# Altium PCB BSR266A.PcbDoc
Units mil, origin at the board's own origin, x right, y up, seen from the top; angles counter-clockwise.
Board outline 1624.02 x 1771.65 mil, 4 copper layers (Top Layer, GND 01, GND 02, Bottom Layer), stack 60.4 mil thick; 39 components, 9 nets, 52 pads, 271 vias.
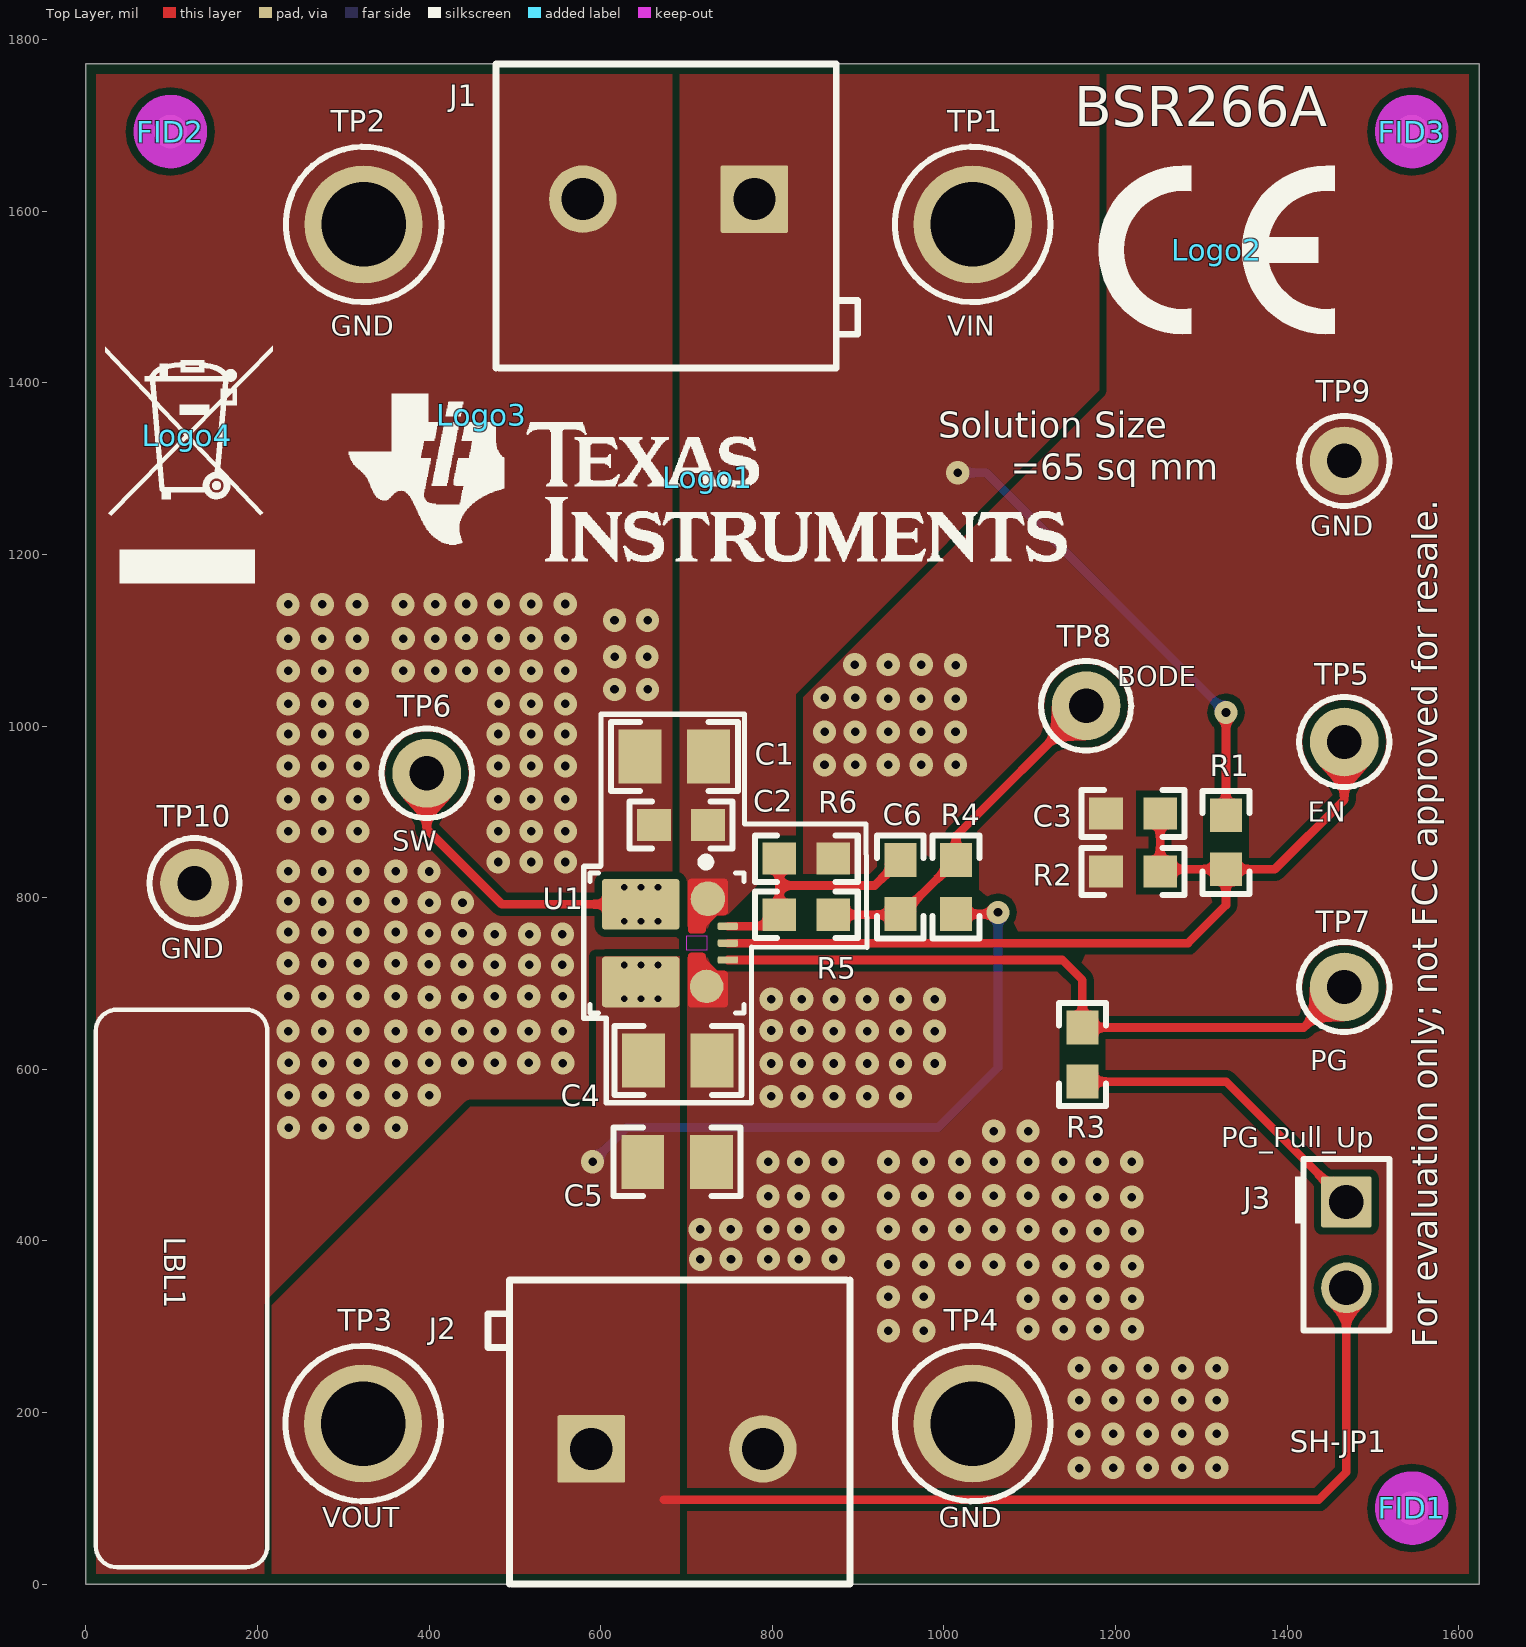
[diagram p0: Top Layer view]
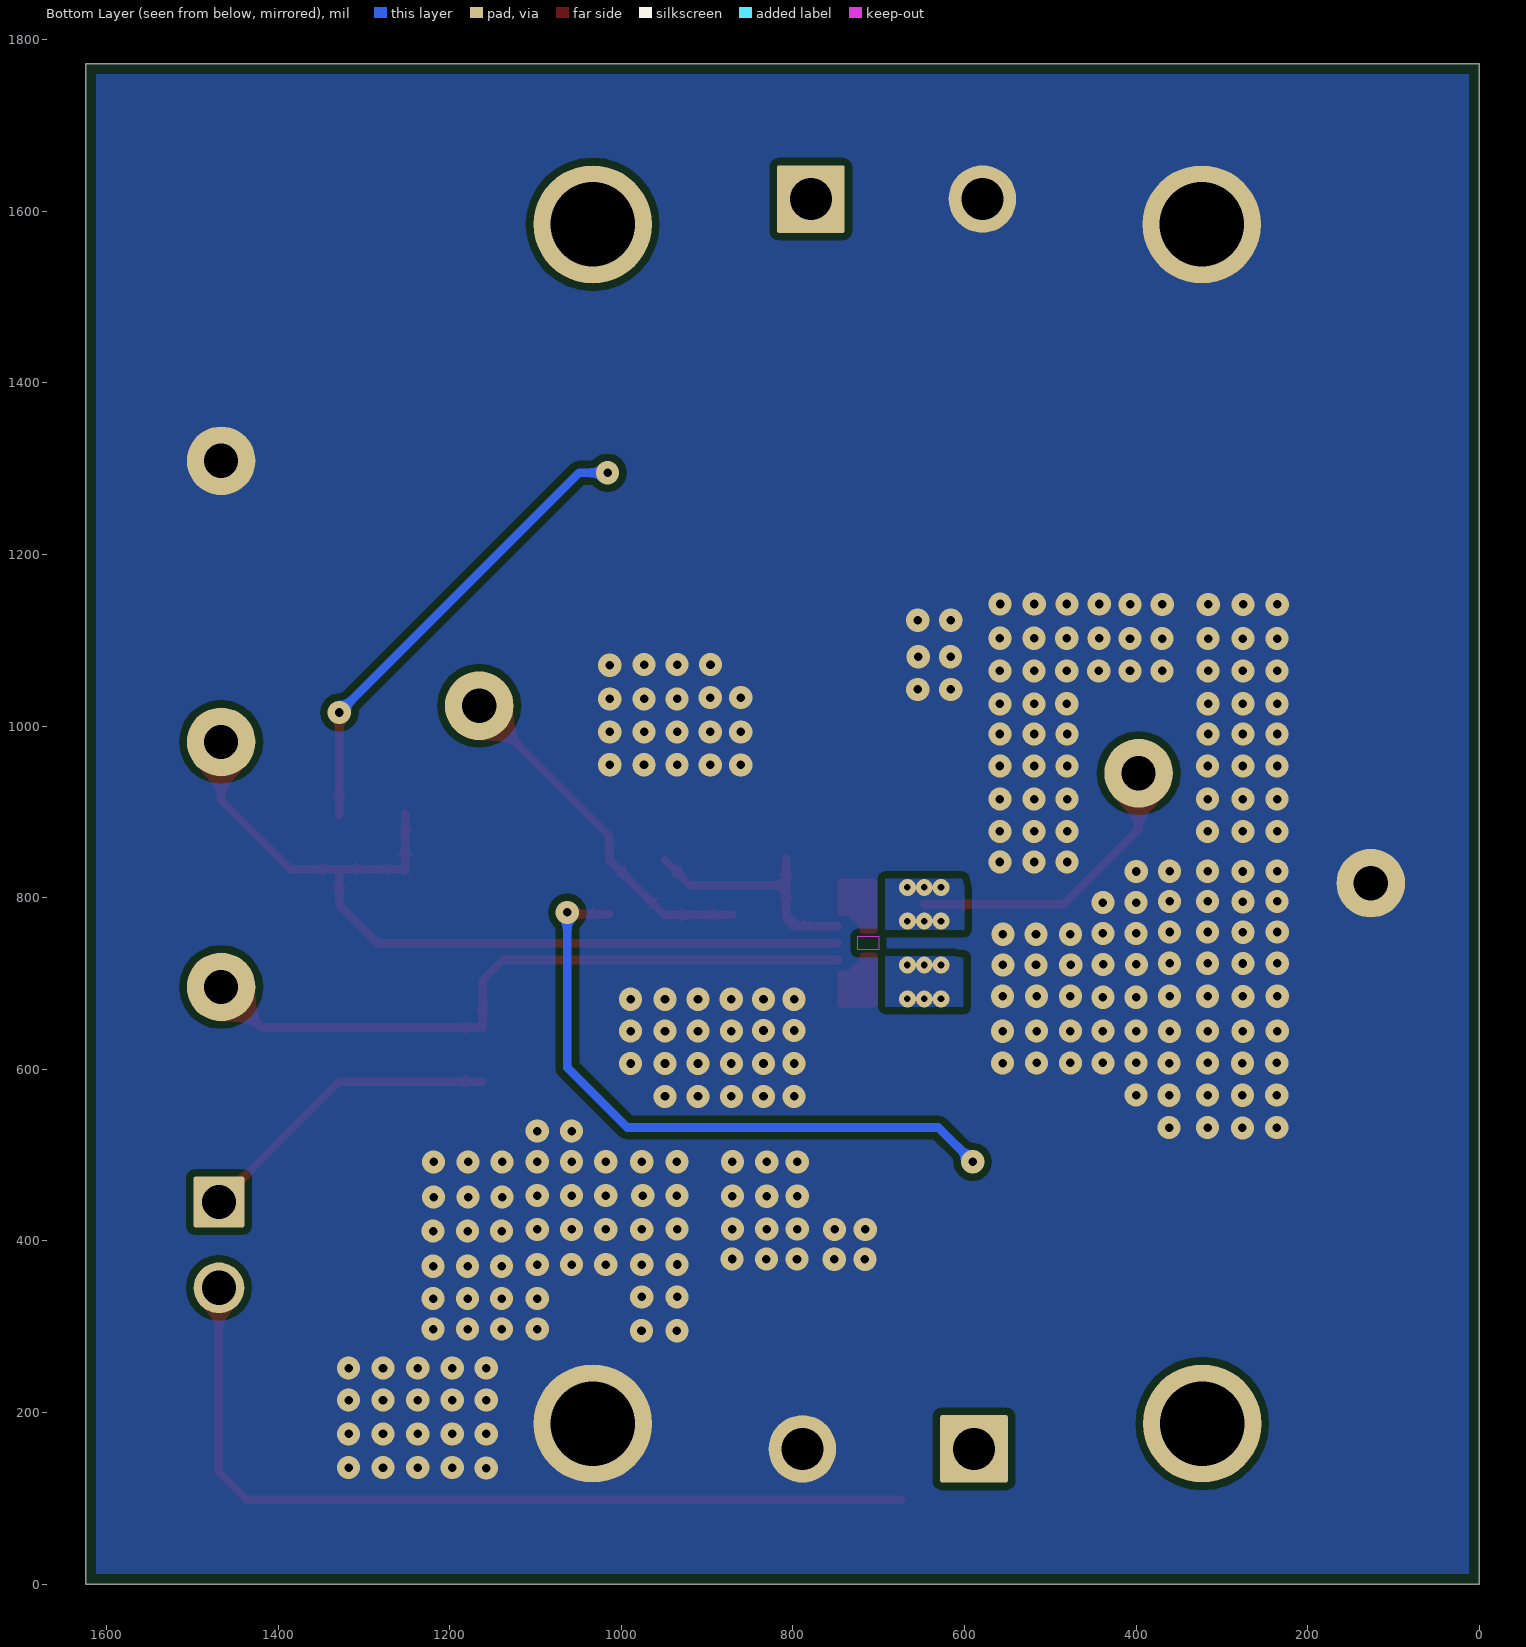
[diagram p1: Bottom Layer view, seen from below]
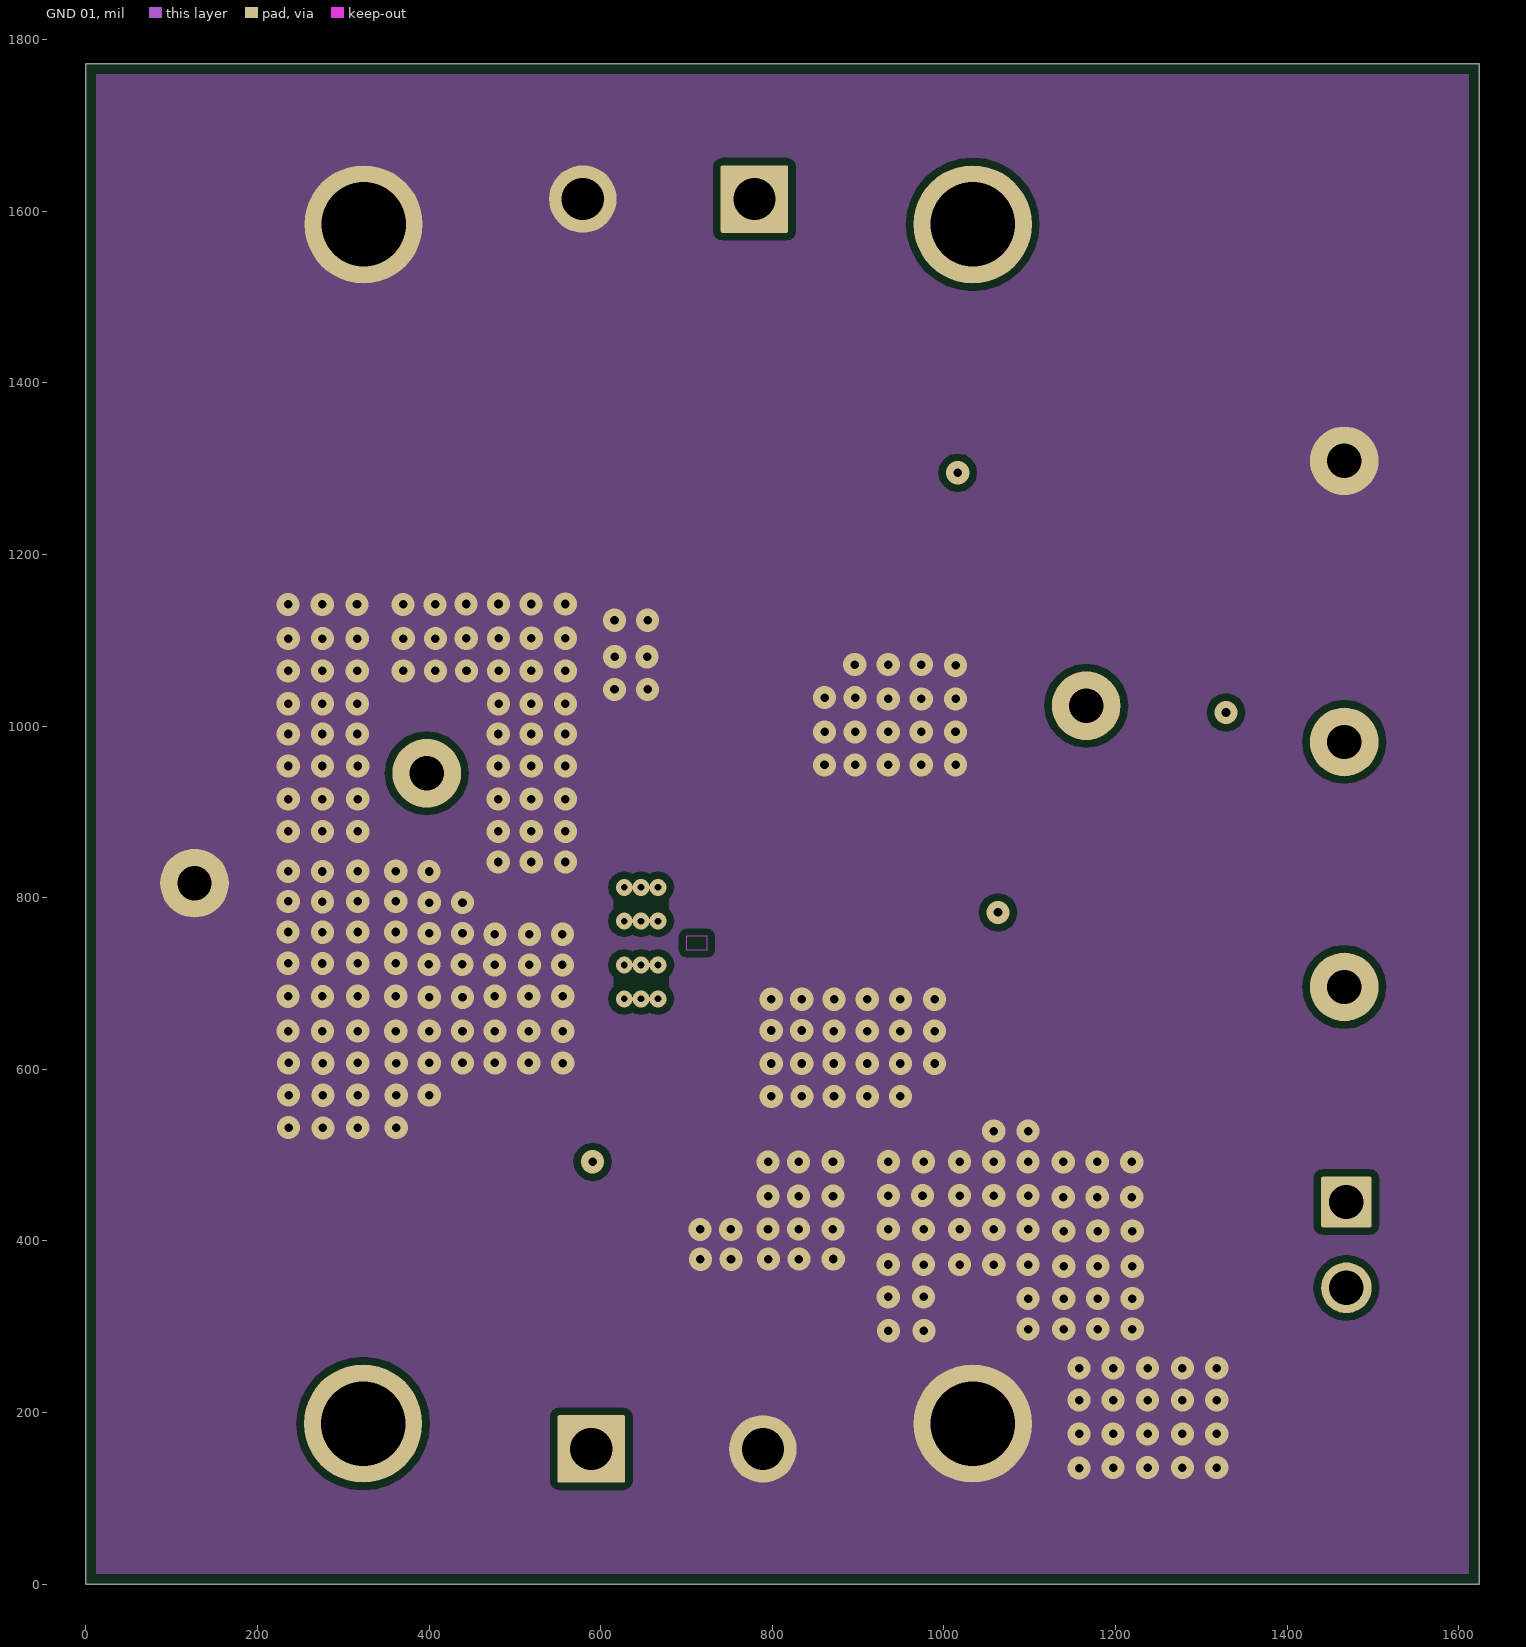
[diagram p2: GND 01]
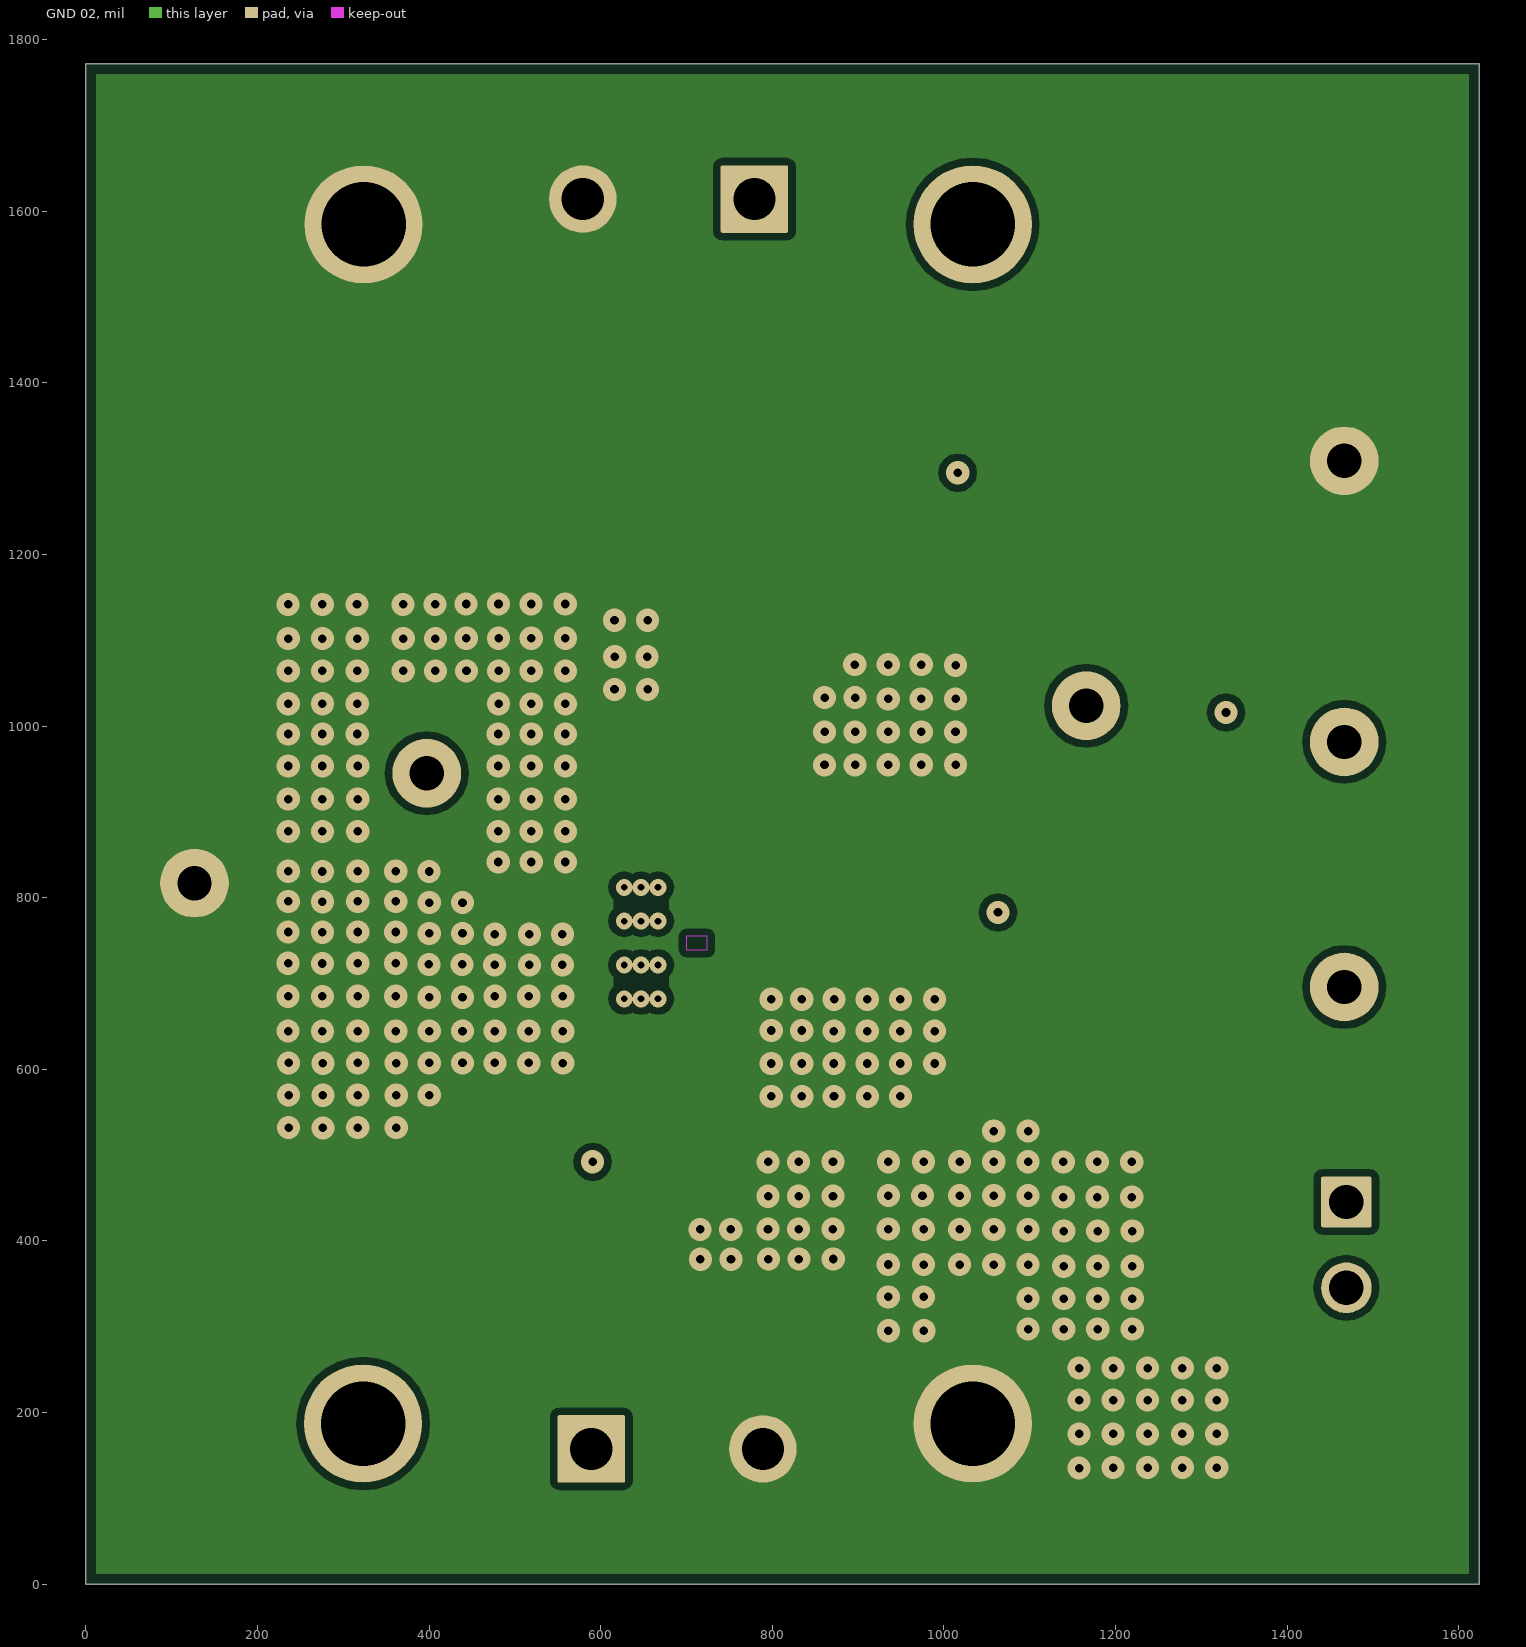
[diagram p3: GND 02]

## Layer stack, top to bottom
Top Solder: solder mask 0.4, Solder Resist, Dk 3.5
Top Layer: signal copper 2.8
Dielectric 1: core 6, FR-4 High Tg, Dk 4.8
GND 01: signal copper 1.4
Dielectric 2: prepreg 40, FR-4 High Tg, Dk 4.8
GND 02: signal copper 1.4
Dielectric 3: core 6, FR-4 High Tg, Dk 4.2
Bottom Layer: signal copper 2.8
Bottom Solder: solder mask 0.4, Solder Resist, Dk 3.5

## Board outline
0,0 0,1771.65 1624.02,1771.65 1624.02,0

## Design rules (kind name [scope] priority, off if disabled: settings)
AcuteAngle [All] p1: minimum=4.50000000000000E+0001 checktracksonly=FALSE
AssemblyTestPointUsage [All] p1: valid=2
BoardOutlineClearance BoardOutlineClearance_MountingHoles [OnCopper and InComponentClass('Mounting Holes')] p1: gap=40 ignorepadtopadclearanceinfootprint=FALSE
BoardOutlineClearance BoardOutlineClearance_Poly [OnCopper and IsPoly] p2: gap=12 ignorepadtopadclearanceinfootprint=FALSE
BoardOutlineClearance [OnCopper and Not InComponentClass('Logo') and not InComponentClass('FiducialMark') and not InRegion(1000,500,4000,800) and not InPoly] p3: gap=75 ignorepadtopadclearanceinfootprint=FALSE
Clearance Clearance_Keepouts [((IsTrack Or IsArc) And Not InPoly) And IsFree and IsKeepOut vs ((IsTrack Or IsArc) And Not InPoly) And IsFree and IsKeepOut] p1: gap=0 ignorepadtopadclearanceinfootprint=FALSE
Clearance Clearance_Poly [InPolygon] p2: gap=8.5 ignorepadtopadclearanceinfootprint=TRUE except(0: Arc-Hole Track-Hole SMDPad-Hole THPad-Hole Via-Hole Fill-Hole Poly-Hole Region-Hole Text-Hole)
Clearance [All] p3: gap=5 ignorepadtopadclearanceinfootprint=FALSE except(0: Arc-Hole Track-Hole SMDPad-Hole THPad-Hole Via-Hole Fill-Hole Poly-Hole Region-Hole Text-Hole)
ComponentClearance ComponentClearance_MountingHoles_FiducialMarks [InComponentClass('Mounting Holes') vs InComponentClass('FiducialMark')] p1: gap=50 collisioncheckmode=3 verticalgap=10 showdistances=FALSE
ComponentClearance ComponentClearance_Shunt [InComponentClass('Header') vs InComponentClass('Shunt')] p2: gap=0 collisioncheckmode=3 verticalgap=0 showdistances=FALSE
ComponentClearance ComponentClearance_Logo [InComponentClass('Logo')] p3: gap=50 collisioncheckmode=3 verticalgap=10 showdistances=FALSE
ComponentClearance ComponentClearance_ScrewToNut [(HasFootprint('NY PMS 440 0025 PH')) vs (HasFootprint('Keystone_1902C'))] p4: gap=5 collisioncheckmode=3 verticalgap=10 showdistances=FALSE
ComponentClearance ComponentClearance_MountingHoles [InComponentClass('Mounting Holes')] p5: gap=250 collisioncheckmode=3 verticalgap=100000 showdistances=FALSE
ComponentClearance ComponentClearance_SmallPassives [HasFootprint('0201*') or HasFootprint('0402*') or HasFootprint('0508') or HasFootprint('0603*') or HasFootprint('0612') or HasFootprint('0805*') or HasFootprint('0815*') or HasFootprint('0830*') or HasFootprint('1206*') or HasFootprint('1210*') or HasFootprint('1808*') or HasFootprint('1812*') or HasFootprint('1825*') or HasFootprint('2010*') or HasFootprint('2220*') or HasFootprint('2225*') or HasFootprint('2512*') or HasFootprint('2728*') or HasFootprint('3518*') vs HasFootprint('0201*') or HasFootprint('0402*') or HasFootprint('0508') or HasFootprint('0603*') or HasFootprint('0612') or HasFootprint('0805*') or HasFootprint('0815*') or HasFootprint('0830*') or HasFootprint('1206*') or HasFootprint('1210*') or HasFootprint('1808*') or HasFootprint('1812*') or HasFootprint('1825*') or HasFootprint('2010*') or HasFootprint('2220*') or HasFootprint('2225*') or HasFootprint('2512*') or HasFootprint('2728*') or HasFootprint('3518*')] p6: gap=14.96 collisioncheckmode=3 verticalgap=10 showdistances=FALSE
ComponentClearance ComponentClearance_THtoSMT [IsThruComponent vs IsSMTComponent] p7: gap=40 collisioncheckmode=3 verticalgap=30 showdistances=FALSE
ComponentClearance ComponentClearance_THtoTH [IsThruComponent vs IsThruComponent] p8: gap=30 collisioncheckmode=3 verticalgap=30 showdistances=FALSE
ComponentClearance [All] p9: gap=30 collisioncheckmode=3 verticalgap=10 showdistances=FALSE
DiffPairsRouting [All] p1: maxlimit=100 minlimit=10 mostfreqgap=10 toplayer_minwidth=15 toplayer_maxwidth=15 toplayer_prefwidth=15 midlayer1_minwidth=15 midlayer1_maxwidth=15 midlayer1_prefwidth=15 midlayer2_minwidth=15 midlayer2_maxwidth=15 midlayer2_prefwidth=15 bottomlayer_minwidth=15 bottomlayer_maxwidth=15 bottomlayer_prefwidth=15 maxuncoupledlength=1000
FabricationTestPointUsage TestPointUsage [All] p1: valid=2 allowmultiple=FALSE
FabricationTestpoint Testpoint [All] p1: side=3 testpointundercomponent=TRUE minsize=40 maxsize=100 preferedsize=60 minholesize=0 maxholesize=40 preferedholesize=32 testpointgrid=1 allowsidetop=TRUE allowsidebottom=TRUE usegrid=TRUE gridtolerance=0.01
FanoutControl Fanout_LCC [IsLCC] p1: bgadir=Out bgaviamode=Centered fanoutstyle=Auto fanoutdirection=Alternating viagrid=1 // Fanout_LCC (Default Rule)
FanoutControl Fanout_BGA [IsBGA] p2: bgadir=Out bgaviamode=Centered fanoutstyle=Auto fanoutdirection=Alternating viagrid=1 // Fanout_BGA (Default Rule)
FanoutControl Fanout_Default [All] p4: bgadir=Out bgaviamode=Centered fanoutstyle=Auto fanoutdirection=Alternating viagrid=1 // Fanout_Default (Default Rule)
FanoutControl Fanout_Small [(CompPinCount < 5)] p5: bgadir=Out bgaviamode=Centered fanoutstyle=Auto fanoutdirection=OutThenIn viagrid=1 // Fanout_Small (Default Rule)
HoleSize [All] p1: absolutevalues=TRUE maxlimit=251 minlimit=7.87 maxpercent=80.000 minpercent=20.000
MinimumAnnularRing MinimumAnnularRing_ThermalPadVias [IsVia and InAnyComponent] p1: minimumring=5.91
MinimumAnnularRing [All] p2: minimumring=6
MinimumSolderMaskSliver MinimumSolderMaskSliver_Logo [InComponentClass('Logo') vs InComponentClass('Logo')] p1: minsoldermaskwidth=0.7
MinimumSolderMaskSliver [All] p2: minsoldermaskwidth=3.94
PlaneClearance [All] p1: clearance=0
PlaneConnect [All] p1: planeconnectstyle=Direct reliefexpansion=10 reliefentries=2 reliefconductorwidth=10 reliefairgap=10
PolygonConnect [All] p1: connectstyle=Direct reliefconductorwidth=10 reliefentries=4 polygonreliefangle="90 Angle" airgapwidth=10
RoutingVias ThermalPadVias [IsVia and InAnyComponent] p1: holewidth=7.87 width=19.68 viastyle="Through Hole" minholewidth=7.87 minwidth=19.68 maxholewidth=12.99 maxwidth=23.62
RoutingVias [All] p2: holewidth=16 width=34 viastyle="Through Hole" minholewidth=7.87 minwidth=26 maxholewidth=40 maxwidth=65
SilkToBoardRegionClearance [Not ((IsComment or IsDesignator) And (Hide <> 'False')) and not InRegion(1000,500,4000,800)] p1:
SilkToSilkClearance SilkToSilkClearance_Pb-FreeLogo [(HasFootprint('Pb-Free_Overlay_Medium') OR HasFootprint('Pb-Free_Overlay_Small')) vs (HasFootprint('Pb-Free_Overlay_Medium') OR HasFootprint('Pb-Free_Overlay_Small'))] p1: silktosilkclearance=0
SilkToSilkClearance [All] p2: silktosilkclearance=4
SilkToSolderMaskClearance SilkToComponentPadClearance [(IsPad or IsFill or IsRegion) and InAnycomponent] p1: minsilkscreentomaskgap=2 clearancetoexposedcopper=TRUE
SilkToSolderMaskClearance "Silk to Solder Mask Opening" [All] p2: minsilkscreentomaskgap=0.5 clearancetoexposedcopper=FALSE
SolderMaskExpansion [All] p1: expansion=1.85 istentingtop=FALSE
Width [All] p1: maxlimit=100 minlimit=3 preferedwidth=10 midlayer1_minwidth=6 midlayer2_minwidth=6 bottomlayer_minwidth=6 minimp=50.000000 maximp=50.000000 favimp=50.000000 checkconnectedcopper=TRUE
14 further rules are at their usual default settings.

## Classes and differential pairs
component class Shunt: SH-JP1
component class Header: J3
component class BSR266A_Sch: C1 C2 C3 C4 C5 C6 J1 J2 J3 R1 R2 R3 R4 R5 R6 TP1 TP2 TP3 TP4 TP5 TP6 TP7 TP8 TP9 TP10 U1
component class Logo: Logo1
component class BSR266A_Hardware: FID1 FID2 FID3 LBL1 Logo1 Logo2 Logo3 Logo4 SH-JP1 ZZ1 ZZ2 ZZ3 ZZ4
component class FiducialMark: FID1 FID2 FID3
component class AssemblyNote: ZZ1 ZZ2 ZZ3 ZZ4
component class Label: LBL1

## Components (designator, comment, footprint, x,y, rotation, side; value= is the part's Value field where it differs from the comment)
C1 "GRM21BR61E106MA73L" 0805_HV 685.69,964.57 r180 top value=10uF
C2 "C0603C104K5RACTU" 0603 693.62,884.82 r180 top value=0.1uF
C3 "C0603X103K5RACTU" 0603 1220.47,898.2 r180 top value=0.01uF
C4 "GRM21BC81C226ME44L" 0805_HV 689.81,610.24 r0 top value=22uF
C5 "GRM21BC81C226ME44L" 0805_HV 688.98,492.13 r0 top value=22uF
C6 "GRM1885C2A330JA01D" 0603 949.12,812.32 r90 top value=33pF
FID1 "Fiducial" Fiducial10-20 1545.28,88.58 r0 top
FID2 "Fiducial" Fiducial10-20 98.43,1692.91 r0 top
FID3 "Fiducial" Fiducial10-20 1545.28,1692.91 r0 top
J1 "ED120/2DS" On-Shore_ED120_2DS 679.13,1614.17 r180 top
J2 "ED120/2DS" On-Shore_ED120_2DS 688.98,157.48 r0 top
J3 "PEC02SAAN" CONN_PEC02SAAN 1469.04,395.27 r270 top
LBL1 "THT-14-423-10" Label_650x200 111.45,344.49 r270 top
Logo1 "Texas Instruments" TI_Stacked_Overlay_Small 724.9,1289.37 r0 top
Logo2 "CE Mark" CE_Mark_5mm 1317.96,1554.88 r0 top
Logo3 "FCC disclaimer" FCC_disclaimer 461.17,1363.06 r0 top
Logo4 "WEEE logo" WEEE_Minimum 118.11,1338.58 r0 top
R1 "CRCW060362K0JNEA" 0603 1328.68,864.5 r90 top value=62k
R2 "CRCW060330K0JNEA" 0603 1220.47,830.56 r0 top value=30k
R3 "CRCW060310K0FKEA" 0603 1161.42,617.12 r270 top value=10.0k
R4 "CRCW060351R0JNEA" 0603 1014,812.32 r270 top value=51
R5 "CRCW06037K50FKEA" 0603 839.54,780.09 r0 top value=7.50k
R6 "CRCW060310K0FKEA" 0603 839.54,845.47 r180 top value=10.0k
SH-JP1 "SNT-100-BK-G" SNT-100-BK-G 1469.04,295.29 r90 top value=1x2
TP1 "1502-2" Keystone1502-2 1033.46,1584.65 r0 top
TP2 "1502-2" Keystone1502-2 323.57,1584.65 r0 top
TP3 "1502-2" Keystone1502-2 322.97,187.01 r0 top
TP4 "1502-2" Keystone1502-2 1033.46,187.01 r0 top
TP5 "5000" Keystone5000 1466.54,981.48 r90 top
TP6 "5000" Keystone5000 397.19,945 r90 top
TP7 "5000" Keystone5000 1466.54,695.86 r90 top
TP8 "5000" Keystone5000 1165.78,1023.62 r90 top
TP9 "5001" Keystone5001 1466.54,1309.05 r90 top
TP10 "5001" Keystone5001 126.5,816.93 r90 top
U1 "TPSM863252RDX" RDX0007A-MFG 673.23,747.03 r270 top
ZZ1 "This Assembly Note is for PCB labels only" AssemblyNoteLabel 1918.6,2707.68 r0 top locked
ZZ2 "These assemblies are ESD sensitive, ESD precautions shall be observed." AssemblyNote 1918.6,2598.8 r0 top locked
ZZ3 "These assemblies must be clean and free from flux and all contaminants. Use of no clean flux is not acceptable." AssemblyNote 1918.6,2510.24 r0 top locked
ZZ4 "These assemblies must comply with workmanship standards IPC-A-610 Class 2, unless otherwise specified." AssemblyNote 1918.6,2421.69 r0 top locked

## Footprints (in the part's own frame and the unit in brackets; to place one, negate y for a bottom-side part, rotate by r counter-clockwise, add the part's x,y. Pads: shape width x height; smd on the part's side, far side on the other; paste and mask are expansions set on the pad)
0603 [mm] "0603 from SM-752 data"
  rect 1x0.95 smd: 1(-0.8,0) 2(0.8,0)
  silkscreen extent -1.52,-0.69 1.52,0.69, body extent -0.87,-0.47 0.87,0.47, height 1
0805_HV [mil] "0805 with 30mil clearance between pads"
  rect 50x63 smd: 1(-40,0) 2(40,0)
  silkscreen extent -74,-40 74,40, body extent -43,-29 43,29, height 57
AssemblyNote [mil] "Assembly Note"
AssemblyNoteLabel [mil] "Assembly Note for PCB Labels"
CE_Mark_5mm [mil] "Minimum text height for CE Mark"
  silkscreen extent -138,-98 138,98
CONN_PEC02SAAN [mm] "SULLINS"
  rrect7% 1.5x1.5 hole 1.016: 1(-1.27,0)
  round 1.5 hole 1.016: 2(1.27,0)
  silkscreen extent -2.54,-1.52 2.54,1.27, body extent -2.54,-1.27 2.54,1.27, height 8.38
FCC_disclaimer [mil]
Fiducial10-20 [mm]
  round 1 smd mask+0.5: 1(0,0)
  Top Layer keep-out circle w1.178: c0,0 r0.5
Keystone1502-2 [mm] "Double Turret"
  round 3.5 hole 2.5: 1(0,0)
  silkscreen extent -2.3,-2.3 2.3,2.3, body extent -1.6,-1.6 1.59,1.6, height 5.62
Keystone5000 [mil] "For Keystone 500x miniature loop terminals"
  round 80 hole 40: 1(0,0)
  silkscreen extent -52,-52 52,52, body extent -49,-49 49,49, height 182
Keystone5001 [mil] "For Keystone 500x miniature loop terminals"
  round 80 hole 40: 1(0,0)
  silkscreen extent -52,-52 52,52, body extent -49,-49 49,49, height 182
Label_650x200 [mil] "Thermal Transfer Label"
  round 1 on Mech13: 0(0,0)
  silkscreen extent -325,-100 325,100, body extent -325,-100 325,100, height 1
On-Shore_ED120_2DS [mm] "ONSHORE"
  rrect5% 2x2 hole 1.25: 1(-2.54,0)
  round 2 hole 1.25: 2(2.54,0)
  silkscreen extent -5.6,-4 5.12,5, body extent -5.78,-4 5.08,5, height 13
RDX0007A-MFG [mm]
  round 1.025 smd paste-1000 mask-1000: 1(-1.312,1.312)
  rrect13% 1.5x2.3 smd paste-1000 mask-1000: 2(-1.15,-0.675) 3(1.15,-0.675)
  round 0.991 smd paste-1000 mask-1000: 4(1.281,1.276)
  rrect45% 0.22x0.6 smd paste+0 mask-1000: 5(0.5,1.9) 6(0,1.9) 7(-0.5,1.9)
  Top Layer region: 1.9,1.8 1.892,1.838 1.871,1.871 1.838,1.892 1.8,1.9 1.8,1.9 0.925,1.9 0.887,1.892 0.854,1.871 0.833,1.838 0.825,1.8 0.825,1.8 0.825,1.634 0.818,1.596 0.796,1.563 0.796,1.563 0.507,1.274 0.474,1.252 0.436,1.245 0.436,1.245 0.39,1.245 0.352,1.237 0.319,1.216 0.298,1.183 0.29,1.145 0.29,1.145 0.29,0.825 0.298,0.787 0.319,0.754 0.352,0.733 0.39,0.725 0.39,0.725 1.8,0.725 1.838,0.733 1.871,0.754 1.892,0.787 1.9,0.825 1.9,0.825
  Top Layer region: -1.9,1.8 -1.887,1.85 -1.85,1.887 -1.8,1.9 -1.8,1.9 -0.925,1.9 -0.887,1.892 -0.854,1.871 -0.833,1.838 -0.825,1.8 -0.825,1.8 -0.825,1.634 -0.818,1.596 -0.796,1.563 -0.796,1.563 -0.507,1.274 -0.474,1.252 -0.436,1.245 -0.436,1.245 -0.39,1.245 -0.34,1.232 -0.303,1.195 -0.29,1.145 -0.29,1.145 -0.29,0.825 -0.298,0.787 -0.319,0.754 -0.352,0.733 -0.39,0.725 -0.39,0.725 -1.8,0.725 -1.838,0.733 -1.871,0.754 -1.892,0.787 -1.9,0.825 -1.9,0.825
  Keep-Out Layer region: -0.2,0.675 0.2,0.675 0.2,1.295 -0.2,1.295
  silkscreen extent -2.52,-2.17 2.07,2.37, body extent -2,-2.1 2,2.3, height 0.25
SNT-100-BK-G [mil] "Samtec STEP model"
  round 1 on Mech3: 0(0,0)
  body extent -100,-50 100,50, height 344
TI_Stacked_Overlay_Small [mil]
  silkscreen extent -418,-98 418,98
WEEE_Minimum [mil] "WEEElie bin"
  silkscreen extent -95,-172 99,104

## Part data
C1: library part CMP-0008303-3, "CAP, CERM, 10 uF, 25 V, +/- 20%, X5R, 0805", Cap_Case=0805, Manufacturer=MuRata, TempCo=X5R, Tolerance_%=20%, Value1=Unknown, Value2=25V, ValueDisplayed=10uF
C2: library part CMP-0006861-3, "CAP, CERM, 0.1 uF, 50 V, +/- 10%, X7R, 0603", Cap_Case=0603, Manufacturer=Kemet, Supplier Part Number 1=399-5089-1-ND, TempCo=X7R, Tolerance_%=10%, Value1=Unknown, Value2=50V, ValueDisplayed=0.1uF
C3: library part CMP-0006978-1, "CAP, CERM, 0.01 uF, 50 V, +/- 10%, X7R, 0603", Cap_Case=0603, Manufacturer=Kemet, Supplier Part Number 1=399-5346-1-ND, TempCo=X7R, Tolerance_%=10%, Value1=Unknown, Value2=50V, ValueDisplayed=0.01uF
C4 C5: library part CMP-0008269-1, "CAP, CERM, 22 uF, 16 V, +/- 20%, X6S, 0805", Cap_Case=0805, Manufacturer=MuRata, Supplier Part Number 1=490-9956-1-ND, TempCo=X6S, Tolerance_%=20%, Value1=Unknown, Value2=16V, ValueDisplayed=22uF
C6: library part CMP-0007263-3, "CAP, CERM, 33 pF, 100 V, +/- 5%, C0G/NP0, 0603", Cap_Case=0603, Manufacturer=MuRata, Supplier Part Number 1=490-1339-1-ND, TempCo=C0G/NP0, Tolerance_%=5%, Value1=Unknown, Value2=100V, ValueDisplayed=33pF
FID1 FID2 FID3: library part CMP-0077181-1, "Fiducial mark.  There is nothing to buy or mount.", Manufacturer=N/A
J1 J2: library part CMP-0074910-1, "Terminal Block, 5.08 mm, 2x1, Brass, TH", Color=Blue, Current_A=15A, Manufacturer="On-Shore Technology", Supplier Part Number 1=ED1609-ND, Voltage_V=300V
J3: library part CMP-0002337-1, "Header, 100mil, 2x1, Tin, TH", Color=Black, Current_A=3A, Manufacturer="Sullins Connector Solutions", Supplier Part Number 1=S1012E-02-ND, Voltage_V=1.8kV
LBL1: library part CMP-0003625-1, "Thermal Transfer Printable Labels, 0.650\" W x 0.200\" H - 10,000 per roll", Manufacturer=Brady, Supplier Part Number 1=97C5133
Logo1: library part CMP-0074838-1, "Texas Instrument Corporate Signature"
Logo2: library part CMP-0074844-1
Logo3: library part CMP-0074847-1, "FCC_disclaimer"
Logo4: library part CMP-0074769-1
R1: library part CMP-0025838-3, "RES, 62 k, 5%, 0.1 W, 0603", Manufacturer=Vishay-Dale, Power_W=100mW, Supplier Part Number 1=541-62KGCT-ND, TempCo="200 ppm/C", Tolerance_%=5%, Value2=0.1W, Value_Code=62k0, ValueDisplayed=62k
R2: library part CMP-0025782-1, "RES, 30 k, 5%, 0.1 W, 0603", Manufacturer=Vishay-Dale, Power_W=100mW, Supplier Part Number 1=541-30KGCT-ND, TempCo="200 ppm/C", Tolerance_%=5%, Value2=0.1W, Value_Code=30k0, ValueDisplayed=30k
R3 R6: library part CMP-0021998-2, "RES, 10.0 k, 1%, 0.1 W, 0603", Manufacturer=Vishay-Dale, Power_W=100mW, Supplier Part Number 1=541-10.0KHCT-ND, TempCo="100 ppm/C", Tolerance_%=1%, Value2=0.1W, Value_Code=10k0, ValueDisplayed=10.0k
R4: library part CMP-0025825-2, "RES, 51, 5%, 0.1 W, 0603", Manufacturer=Vishay-Dale, Power_W=100mW, Supplier Part Number 1=541-51GCT-ND, TempCo="200 ppm/C", Tolerance_%=5%, Value2=0.1W, Value_Code=51R0, ValueDisplayed=51
R5: library part CMP-0022601-1, "RES, 7.50 k, 1%, 0.1 W, 0603", Manufacturer=Vishay-Dale, Power_W=100mW, Supplier Part Number 1=541-7.50KHCT-ND, TempCo="100 ppm/C", Tolerance_%=1%, Value2=0.1W, Value_Code=7k50, ValueDisplayed=7.50k
SH-JP1: library part CMP-0003623-1, "Shunt, 100mil, Gold plated, Black", Alternate Manufacturer=3M, Alternate PartNumber=969102-0000-DA, Manufacturer=Samtec, Supplier Part Number 1=SNT-100-BK-G-ND
TP1 TP2 TP3 TP4: library part CMP-0055113-1, "Terminal, Turret, TH, Double", Manufacturer=Keystone, Supplier Part Number 1=36-1502-2-ND
TP5 TP6 TP7 TP8: library part CMP-0055137-1, "Test Point, Miniature, Red, TH", Color=Red, Manufacturer=Keystone, Supplier Part Number 1=36-5000-ND
TP9 TP10: library part CMP-0055138-1, "Test Point, Miniature, Black, TH", Color=Black, Manufacturer=Keystone, Supplier Part Number 1=36-5001-ND
U1: library part CMP-0097277-1, "3V to 16 V Input, 3-A Synchronous Step-Down Voltage Regulator Module, QFN-FCMOD7", Manufacturer="Texas Instruments", Max Supply Voltage=16V, Min Supply Voltage=3V, Nominal Supply Current=120-400uA, Operating Temperature Range="-40°C to +125°C", Output Voltage=0.6-7V, Switching Frequency=1400/2000kHz
ZZ1: library part CMP-0003616-3
ZZ2: library part CMP-0077236-1
ZZ3: library part CMP-0077237-1
ZZ4: library part CMP-0077238-1

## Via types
v1: diameter 27, hole 10, Top Layer to Bottom Layer, 259 vias
v2: diameter 19.68, hole 7.87, Top Layer to Bottom Layer, 12 vias

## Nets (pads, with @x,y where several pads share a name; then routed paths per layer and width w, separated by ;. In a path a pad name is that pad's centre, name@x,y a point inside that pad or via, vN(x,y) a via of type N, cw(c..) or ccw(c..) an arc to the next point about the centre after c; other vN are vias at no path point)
EN: C3.1 R1.1 R2.2 TP5.1 U1.6 | length 1025
  Top Layer w10: U1.6 1284.45,747.03 1328.68,791.27 R1.1 ; C3.1 R2.2 1254.42,833.01 R1.1 ; TP5.1 1466.54,913.96 1385.59,833.01 R1.1
FB: C6.2 R5.1 R6.2 U1.7 | length 295.7
  Top Layer w10: U1.7 794.67,766.71 R5.1 808.05,814.15 ; R5.1@799.97,766.71 R5.1@808.05,774.78 ; R6.2 808.05,814.15 ; C6.2 919.46,814.15 808.05,814.15
GND: C1.2 C2.2 C3.2 C4.2 C5.2 J1.2 J2.2 R2.1 R6.1 TP2.1 TP4.1 TP9.1 TP10.1 U1.4
  other v1: 1157.46,135.1 1197.18,135.65 1237.29,135.65 1277.84,135.65 1317.96,135.65 1157.46,175.02 1197.18,175.02 1237.29,175.02 1277.84,175.02 1317.96,175.02 1157.46,214.39 1197.18,214.39 1237.29,214.39 1277.84,214.39 1317.96,214.39 1157.46,251.67 1197.18,251.67 1237.29,251.67 1277.84,251.67 1317.96,251.67 935.3,295.28 976.58,295.28 1098.13,297.07 1139.52,297.07 1179.24,297.07 1219.36,297.07 1098.13,332.68 1139.52,332.68 1179.24,332.68 1219.36,332.68 935.04,334.65 976.32,334.65 1139.52,370.39 1179.24,370.39 1219.36,370.39 935.04,372.39 976.32,372.36 1018.29,372.36 1058.01,372.36 1098.13,372.36 716.13,378.49 751.8,378.49 795.31,378.74 830.99,378.74 871,378.82 1139.52,411.42 1179.24,411.42 1219.36,411.42 715.75,413.39 751.42,413.39 976.32,413.39 1018.29,413.39 1058.01,413.39 1098.13,413.39 794.93,413.64 830.6,413.64 870.61,413.72 935.04,413.69 1138.96,451.02 1178.69,451.02 1218.8,451.02 794.98,452.04 830.6,452.04 870.66,452.12 935.3,452.76 975.03,452.76 1018.29,452.76 1058.01,452.76 1098.13,452.76 794.98,492.04 830.6,492.04 870.66,492.13 935.3,492.13 976.32,492.13 1018.29,492.13 1058.01,492.13 1098.13,492.13 1138.96,492.04 1178.69,492.04 1218.8,492.04 1058.01,527.83 1098.13,527.83 236.14,531.96 276.12,531.69 316.69,531.96 361.57,531.96 798.69,568.36 834.37,568.36 871.81,568.36 910.7,568.36 949.18,568.36 236.14,569.87 276.12,569.59 316.69,569.87 361.57,569.7 400.07,569.87 236.14,607.33 276.12,607.06 316.69,607.33 361.57,607.17 400.07,607.33 438.83,607.33 476.63,607.33 516.06,607.33 555.68,607.17 798.64,606.72 834.31,606.72 871.76,606.72 910.65,606.72 949.18,606.72 989.17,606.72 235.61,644.49 275.59,644.21 316.69,644.49 361.04,644.32 400.07,644.49 438.83,644.49 476.63,644.49 516.06,644.49 555.68,644.32 871.76,644.49 910.65,644.49 949.18,644.49 989.17,644.49 798.69,645.12 834.31,645.12 798.69,681.58 834.31,681.58 871.94,681.58 910.65,681.58 949.18,681.58 989.17,681.58 400.07,683.88 438.83,683.88 235.61,685.16 275.59,684.89 316.69,685.16 361.04,685.16 476.63,685.16 516.06,685.16 555.68,685.16 399.71,722.2 438.46,722.2 476.27,721.68 516.79,721.68 555.32,721.68 235.61,723.47 275.59,723.2 316.69,723.47 361.04,723.47 476.63,757.34 516.79,757.34 555.32,757.34 400.07,758.25 438.83,758.25 235.61,759.94 275.59,759.67 316.69,759.94 361.04,759.94 400.07,794.27 438.83,794.27 275.59,795.28 235.81,795.55 316.69,795.55 361.04,795.55 235.81,830.78 275.59,830.5 316.69,830.78 361.04,830.78 399.93,830.5 480.44,841.52 518.97,841.52 558.78,841.52 235.81,877.17 275.59,877.17 316.69,877.17 480.44,877.17 518.97,877.17 558.78,877.17 235.81,914.91 275.59,914.91 316.69,914.91 480.55,914.91 518.97,914.91 558.78,914.91 235.81,953.44 275.59,953.44 316.69,953.44 480.55,953.44 518.97,953.44 558.78,953.44 860.8,954.72 896.47,954.72 935.04,954.87 973.59,954.87 1013.52,954.87 235.81,990.72 275.59,990.72 316.11,990.72 480.55,990.72 518.97,990.72 558.78,990.72 860.85,993.13 896.47,993.13 934.99,993.23 973.54,993.23 1013.47,993.23 235.81,1025.99 275.59,1025.99 316.11,1025.99 480.99,1025.99 518.97,1025.81 558.78,1025.81 935.04,1031.63 973.54,1031.63 1013.52,1031.63 860.85,1033.13 896.47,1033.13 616.05,1042.66 654.58,1042.66 235.81,1064.25 275.59,1064.25 316.11,1064.25 369.76,1064.25 407.2,1064.25 443.55,1064.25 480.99,1064.25 518.97,1064.25 558.78,1064.25 1013.52,1070.87 896.11,1071.64 935.04,1071.64 973.54,1071.64 616.21,1080.76 654.02,1080.76 235.81,1101.84 275.59,1101.84 316.11,1101.84 369.76,1101.84 407.2,1101.84 443.19,1102.36 480.99,1102.36 518.97,1102.36 558.78,1102.36 616.05,1123.31 654.58,1123.31 235.61,1141.73 275.39,1141.73 315.91,1141.73 369.56,1141.73 407,1141.73 442.99,1142.25 480.79,1142.25 518.77,1142.25 558.58,1142.25
NetC6_1: C6.1 R4.1 R5.2 TP8.1 | length 412
  Top Layer w10: R5.2 948.38,780.09 C6.1 951,780.82 R4.1 1014,871.83 TP8.1
NetJ3_1: J3.1 R3.2 | length 365.8
  Top Layer w10: R3.2 1328.68,585.62 J3.1
PG: R3.1 TP7.1 U1.5 | length 803.1
  Top Layer w10: U1.5 1137.99,727.34 1161.42,703.92 R3.1 1419.29,648.61 TP7.1
SW: TP6.1 U1.2 | length 351
  Top Layer w10: TP6.1 397.19,879.68 484.57,792.3 U1.2
  other v2: 627.36,772.62 647.05,772.62 666.73,772.62 627.36,811.99 647.05,811.99 666.73,811.99
Vin: C1.1 C2.1 J1.1 R1.2 TP1.1 U1.1 | length 548.2
  Top Layer w10: R1.2 1328.68,1015.72 v1(1328.74,1015.77)
  Bottom Layer w10: v1(1016.06,1295.19) 1049.33,1295.19 v1(1328.74,1015.77)
VOUT: C4.1 C5.1 J2.1 J3.2 R4.2 TP3.1 U1.3 | length 1772.1
  Top Layer w10: 673.62,98.43 1437.01,98.43 1469.04,130.45 J3.2 ; R4.2 1061.05,780.82 v1(1062.99,782.77)
  Bottom Layer w10: v1(590.55,492.13) 630.55,532.13 993.24,532.13 1062.99,601.87 v1(1062.99,782.77)
  other v2: 627.36,682.07 647.05,682.07 666.73,682.07 627.36,721.44 647.05,721.44 666.73,721.44
pads on no net: FID1.1 FID2.1 FID3.1 LBL1.0 SH-JP1.0

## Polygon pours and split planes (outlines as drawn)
GND on Top Layer "TOP_LAYER_GND_P106" (solid, remove dead copper, pour order 106): 0,1771.65 1624.02,1771.65 1624.02,0 0,0
Vin on Top Layer "TOP_LAYER_VIN_P076" (solid, remove dead copper, pour order 76): 688.98,1771.65 691.82,1768.81 691.82,757.34 725.22,757.34 827.04,859.16 827.04,1037.1 1181.1,1391.16 1181.1,1771.65 692.91,1771.65
VOUT on Top Layer "TOP_LAYER_VOUT_P074" (solid, remove dead copper, pour order 74): 593.49,732.16 594.17,731.47 692.16,731.47 692.16,0 216.54,0 216.54,324.8 447.83,556.1 594.49,556.1 594.49,730.94 594.21,731.21
GND on Bottom Layer "BOTTOM_LAYER_GND_P100" (solid, remove dead copper, pour order 100): 0,1771.65 1624.02,1771.65 1624.02,0 0,0
VOUT on Bottom Layer "BOTTOM_LAYER_VOUT_P044" (solid, remove dead copper, pour order 44): 600.92,730.49 601.91,731.47 692.16,731.47 692.16,672.22 691.56,672.82 601.29,672.82 601.29,730.12
SW on Bottom Layer "BOTTOM_LAYER_SW_P036" (solid, remove dead copper, pour order 36): 602.74,821.83 692.52,821.83 692.52,761.14 691.09,762.58 600.56,762.58 600.56,821.01 603.1,823.55
GND on GND 02 "GND_02_GND_P102" (solid, remove dead copper, pour order 102): 0,1771.65 1624.02,1771.65 1624.02,0 0,0
GND on GND 01 "GND_01_GND_P104" (solid, remove dead copper, pour order 104): 0,1771.65 1624.02,1771.65 1624.02,0 1614.17,-9.84 0,-9.84

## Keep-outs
Keep-Out Layer:
  text ".Layer_Name" at 577,-858.49 h60

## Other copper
Top Layer:
  text ".Layer_Name" at 577,-858.49 h60
Bottom Layer:
  text ".Layer_Name" at 577,-858.49 h60

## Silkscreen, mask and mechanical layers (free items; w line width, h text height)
Top Overlay:
  lines w3.97: 580.2,836.18 580.64,836.61 ; 599.47,836.61 600.2,837.34
  lines w6: 580.2,836.18 580.2,659.45 604.92,659.45 ; 580.64,836.61 599.47,836.61 ; 600.2,837.34 600.2,1013.78 767.72,1013.78 767.72,885.83 909.03,885.83 910.26,741.88 775.77,742.43 775.77,561.02 606.45,561.02 606.45,659.45
  text "BSR266A" at 1151.57,1683.07 h80
  text "GND" at 285.43,1446.85 h40
  text "VIN" at 1004.07,1446.85 h40
  text "Solution Size" at 993.53,1335.9 h30
  text "=65 sq mm" at 1077.86,1287.19 h30
  text "GND" at 1427.17,1213.68 h40
  text "BODE" at 1201.77,1038.2 h40
  text "EN" at 1423.92,880.55 h40
  text "SW" at 357.04,846.77 h40
  text "GND" at 87.41,721.44 h40
  text "PG" at 1427.17,590.55 h40
  text "PG_Pull_Up" at 1322.98,500.71 h40
  text "VOUT" at 275.59,58.07 h40
  text "GND" at 994.09,58.07 h40
  text ".Layer_Name" at 577,-858.49 h40
Bottom Overlay:
  text ".Layer_Name" at 577,-858.49 h60
Top Paste:
  text ".Layer_Name" at 577,-858.49 h60
Bottom Paste:
  text ".Layer_Name" at 577,-858.49 h60
Top Solder:
  text ".Layer_Name" at 577,-858.49 h60
  text ".Layer_Name" at 577,-858.49 h60
Bottom Solder:
  text ".Layer_Name" at 577,-858.49 h60
Drill Guide:
  text ".Layer_Name" at 577,-858.49 h60
M1 Board Outline:
  the board outline again, w10
  text ".Layer_Name" at 577,-858.49 h60
M2 Board Dimensions:
  rectangle: 0,-275 125,-150
  rectangle: 125,-400 500,-275
  lines w7: 0,-275 1000,-275 ; 125,-400 125,-150 ; 250,-400 250,-150 ; 500,-400 500,-150 ; 750,-400 750,-150 ; 0,-400 1000,-400 1000,-150 0,-150 0,-400
  text ".Layer_Name" at 577,-858.49 h60
M3 3D STEP Top:
  text ".Layer_Name" at 577,-858.49 h60
M4 3D STEP Bottom:
  text ".Layer_Name" at 577,-858.49 h60
M5 Assembly Top:
  lines w10: -292,-930.17 6308,-930.17 ; -292,-726.83 6310,-726.83 ; -292,-523.5 -292,-1133.5 3713,-1133.5 6310,-1133.5 6310,-523.5 -291.5,-523.5 -291.5,-1133.5 1284,-1133.5 ; 2173,-1133.5 2173,-523.5 ; 3440,-726.83 3440,-523.5 ; 4280,-726.83 4280,-523.5 ; 4902,-1140 4902,-937.17
  text "COMPONENTS MARKED 'DNP' SHOULD NOT BE POPULATED." at 1153.5,-318.5 h60
  text "ASSEMBLY VARIANT:" at 1153,-434 h60
  text ".VariantName" at 2189,-434 h60
  text "PCB VIEWED FROM TOP SIDE" at -228.5,-655.67 h60
  text "BOARD #:" at 2248,-655.67 h60
  text ".PRJ_Number" at 2793.5,-655.67 h60
  text "REV:" at 3638,-655.67 h60
  text ".PCB_Rev" at 3929.5,-655.67 h60
  text "SVN REV:" at 4476,-655.67 h60
  text ".VersionControl_RevNumber" at 4982,-655.67 h60
  text "TID #:" at 2248,-859 h60
  text ".TID" at 2793.5,-859 h60
  text "PLOT NAME =" at -228.5,-1064.34 h60
  text ".plot_File_Name" at 577,-1064.34 h60
  text "GENERATED    :" at 2250,-1064.34 h60
  text ".Print_Date" at 3119.5,-1064.34 h60
  text ".Print_Time" at 3848.5,-1064.34 h60
  text "TEXAS INSTRUMENTS" at 5113,-1064.34 h60
M6 Assembly Bottom:
  lines w10: -292.5,-727.33 6309.5,-727.33 ; -290.5,-930.67 6309.5,-930.67 ; 1115.5,-1140.5 1115.5,-937.67 ; 1737.5,-727.33 1737.5,-524 ; 2577.5,-727.33 2577.5,-524 ; 3844.5,-1134 3844.5,-524 ; 4733.5,-1134 6309,-1134 6309,-524 -292.5,-524 -292.5,-1134 2304.5,-1134 6309.5,-1134 6309.5,-524
  text "COMPONENTS MARKED 'DNP' SHOULD NOT BE POPULATED." at 6102,-318 h60
  text ".VariantName" at 5058,-434 h60
  text "ASSEMBLY VARIANT:" at 6097,-434 h60
  text ".VersionControl_RevNumber" at 1035.5,-656.17 h60
  text "SVN REV:" at 1541.5,-656.17 h60
  text ".PCB_Rev" at 2088,-656.17 h60
  text "REV:" at 2379.5,-656.17 h60
  text ".PRJ_Number" at 3224,-656.17 h60
  text "BOARD #:" at 3769.5,-656.17 h60
  text "PCB VIEWED FROM BOTTOM SIDE" at 6246,-656.17 h60
  text ".TID" at 3224,-859.5 h60
  text "TID #:" at 3769.5,-859.5 h60
  text "TEXAS INSTRUMENTS" at 904.5,-1064.84 h60
  text ".Print_Time" at 2169,-1064.84 h60
  text ".Print_Date" at 2898,-1064.84 h60
  text "GENERATED    :" at 3767.5,-1064.84 h60
  text ".plot_File_Name" at 5440.5,-1064.84 h60
  text "PLOT NAME =" at 6246,-1064.84 h60
M9 Title Sheet:
  drawing of 57 lines, arcs and shapes, not listed
  text "1" at 739.84,8036.5 h70
  text "2" at 3235.5,8036.5 h70
  text "3" at 5724.84,8036.5 h70
  text "4" at 8231.51,8036.5 h70
  text "5" at 10730.5,8036.5 h70
  text "6" at 13235.5,8036.5 h70
  text "A" at -416.5,6893.5 h70
  text "A" at 14383.5,6893.5 h70
  text "B" at -416.5,4513.5 h70
  text "B" at 14383.5,4513.5 h70
  text "C" at -416.5,2138.5 h70
  text "C" at 14383.5,2138.5 h70
  text "PROJECT TITLE:" at 11343.5,277.5 h45
  text ".PRJ_Title" at 11393.5,144.17 h70
  text "DESIGNED FOR:" at 11343.5,-23.5 h45
  text ".PRJ_Customer" at 11393.5,-163.5 h70
  text "D" at -416.5,-231.5 h70
  text "D" at 14383.5,-231.5 h70
  text "FILE NAME:" at 11343.5,-323.5 h45
  text ".PCB_File_Name_No_Path" at 11393.5,-443.5 h70
  text "Texas Instruments (TI) and/or its licensors do not warrant the accuracy or completeness of this specification" at 6374,-605.34 h45
  text "ENGINEER:" at 11343.5,-613.5 h45
  text "LAYOUT BY:" at 12848.5,-613.5 h45
  text "or any information contained therein. TI and/or its licensors do not warrant that this design will meet" at 6329.01,-718 h45
  text ".PRJ_Engineer" at 11393.5,-768.49 h70
  text ".PCB_Layout" at 12899,-768.49 h70
  text "the specifications, will be suitable for your application or fit for any particular purpose, or will operate in" at 6329.01,-830.67 h45
  text ".Layer_Name" at 577,-858.49 h60
  text "ALTIUM DESIGNER VERSION:" at 12848.5,-923.5 h45
  text "an implementation. TI and/or its licensors do not warrant that the design is production worthy. You should" at 6329.01,-943.33 h45
  text "completely validate and test your design implementation to confirm the system functionality for your application." at 6374,-1056 h45
  text ".print_Scale" at 11393.5,-1056.83 h70
  text ".Application_BuildNumber" at 12899,-1056.83 h70
  text "1" at 739.84,-1263.5 h70
  text "2" at 3235.5,-1263.5 h70
  text "3" at 5724.84,-1263.5 h70
  text "4" at 8231.51,-1263.5 h70
  text "5" at 10730.5,-1263.5 h70
  text "6" at 13235.5,-1263.5 h70
M10 Fab Notes:
  drawing of 189 lines, arcs and shapes, not listed
  text "DESIGN INFORMATION" at 12382.02,6356.17 h60
  text "MIN. TRACK WIDTH:" at 11737.46,6224.05 h60
  text "8" at 12833.7,6224.05 h60
  text "MIL" at 12988.46,6224.05 h60
  text "MIN. CLEARANCE:" at 11737.46,6099.92 h60
  text "0.2" at 12773.7,6099.93 h60
  text "mm" at 12988.46,6099.92 h60
  text "MIN. VIA PAD SIZE:" at 11737.46,5975.8 h60
  text "24" at 12803.71,5975.8 h60
  text "MIL" at 12988.46,5975.8 h60
  text "0.05mm (2MIL)" at 12432.46,5845.9 h60
  text "MINIMUM ANNULAR RING" at 11408.23,5837.67 h60
  text "EXTERNAL" at 13140.46,5837.67 h60
  text "PER" at 11608.23,5727.55 h60
  text "IPC-D-275 CLASS 2 LEVEL C" at 11828.23,5727.54 h60
  text "MIL, HOLES" at 13316.46,5627.07 h60
  text "+/-" at 12924,5618.48 h60
  text "+/-" at 13778,5618.48 h60
  text "REGISTRATION TOLERANCES:" at 11408.23,5617.42 h60
  text "METAL" at 12608,5617.42 h60
  text "5" at 13184.2,5617.42 h60
  text "3" at 14017.2,5617.42 h60
  text "MIL" at 14133.46,5617.42 h60
  text "HOLE SIZE TOLERANCE (UNLESS OTHERWISE SPECIFIED):" at 11408.23,5519.1 h60
  text "+/-" at 13778,5516.23 h60
  text "3" at 14017.2,5515.17 h60
  text "MIL" at 14133.46,5515.17 h60
  text "MATERIAL:" at 11333.46,5377.52 h60
  text "FR-4 High Tg" at 12319.9,5249 h60
  text "X" at 12175.46,5241.01 h60
  text "FR-408" at 11754.46,5236.49 h60
  text "OTHER" at 13242.46,5236.49 h60
  text "62 MIL (1.6mm) +/-10%" at 12074.56,5093.46 h60
  text "X" at 11954.46,5091.01 h60
  text "THICKNESS:" at 11408.23,5085.24 h60
  text "OTHER" at 13359.46,5085.24 h60
  text "TOLERANCE:" at 11408.23,4946.92 h60
  text "X" at 12256.46,4946.92 h60
  text "ANSI IPC-6012 TYPE 3 CLASS 2" at 12434.48,4946.92 h60
  text "OTHER +/-" at 12434.46,4802.73 h60
  text "BOW & TWIST:" at 11408.23,4657.54 h60
  text "X" at 12256.46,4657.54 h60
  text "ANSI IPC-6012 TYPE 3 CLASS 2" at 12434.48,4657.54 h60
  text "OTHER +/-" at 12434.46,4510.85 h60
  text "DRILLING:" at 11333.46,4380.23 h60
  text "NC_DRILL FILES" at 13094.46,4275.04 h60
  text "REFERENCE:" at 11408.23,4271.1 h60
  text "X" at 12065.46,4271.01 h60
  text "AS SHOWN" at 12243.46,4271.1 h60
  text "X" at 12966.46,4271.1 h60
  text "OTHER" at 13392.46,4128.85 h60
  text "PTH COPPER THICKNESS:" at 11407.91,4125.32 h60
  text "X" at 12547.14,4125.32 h60
  text "20-30 um" at 12675.14,4125.32 h60
  text "BOARD FINISH:" at 11333.46,3977.73 h60
  text "SILKSCREEN:" at 11488.68,3867.6 h60
  text "X" at 12446.46,3867.6 h60
  text "TOP" at 12563.46,3867.6 h60
  text "X" at 12956.46,3867.6 h60
  text "BOTTOM" at 13074.46,3867.6 h60
  text "SILKSCREEN COLOR:" at 11488.68,3712.41 h60
  text "X" at 12445.46,3712.41 h60
  text "WHITE" at 12563.46,3712.41 h60
  text "OTHER" at 13074.46,3712.41 h60
  text "X" at 12576.46,3568.96 h60
  text "GREEN" at 12694.46,3568.96 h60
  text "OTHER" at 13312.46,3568.96 h60
  text "SOLDER RESIST COLOR:" at 11488.68,3562.1 h60
  text "X" at 12576.46,3414.71 h60
  text "MATTE" at 12694.46,3414.71 h60
  text "SEMI-GLOSS" at 13312,3414.07 h60
  text "IMMERSION GOLD (ENIG)" at 12394.46,3241.94 h60
  text "ENEPIG" at 13732,3234.72 h60
  text "SURFACE FINISH:" at 11333.46,3233.72 h60
  text "X" at 12216.46,3233.72 h60
  text "IMM. TIN/SILVER OR EQUIV" at 11663,3096.4 h60
  text "OTHER" at 13094.46,3092.47 h60
  text "ARRAY/PANEL:" at 11333.46,2937.09 h60
  text "CUT AND TRIM PER M1 BOARD OUTLINE" at 12394.46,2928.87 h60
  text "N.C. ROUTE" at 12394.46,2792.9 h60
  text "X" at 13082.46,2792.9 h60
  text "V. SCORE" at 13260.46,2792.9 h60
  text "CERTIFICATION:" at 11333.46,2663.77 h60
  text "MATERIALS AND WORKMANSHIP FOR ALL PCBS" at 12058.46,2663.77 h60
  text "TO MEET OR EXCEED THE REQUIREMENTS OF:" at 12058.46,2569.71 h60
  text "X" at 11695.97,2441.08 h60
  text "ANSI IPC-A-600F CLASS ->" at 11823.96,2441.08 h60
  text "X" at 13471.97,2441.08 h60
  text "2" at 13581.96,2441.08 h60
  text "1" at 13266.96,2439.58 h60
  text "3" at 13935.96,2439.58 h60
  text "X" at 12507.97,2293.39 h60
  text "RoHS" at 12635.96,2293.39 h60
  text "OTHER" at 13280.36,2293.39 h60
  text "PER ORDER" at 13677.42,2293.39 h60
  text "ALL BOARDS MUST MEET OR EXCEED UL94-V0 REQUIREMENTS." at 11361,2139.57 h60
  text "PCB MUST BEAR THE UL94V-0 UL REGISTERED MATERIAL ID NUMBER" at 11361,2023.5 h60
  text "ADDITIONAL REQUIREMENTS:" at 11333.46,1854.08 h60
  text "MICROSECTION:" at 11408.23,1746.95 h60
  text "YES" at 12313.96,1746.95 h60
  text "REQUIRED" at 13175.46,1602.62 h60
  text "BARE BOARD ELEC. TEST:" at 11408.23,1599.76 h60
  text "NONE" at 12713.96,1599.76 h60
  text "X" at 13057.46,1599.76 h60
  text "PER ORDER" at 13767.46,1599.76 h60
  text "XX MIL VIAS REQUIRE NON-CONDUCTIVE FILL AND PLANARIZE" at 11576.38,1394.82 h59
  text "XX MIL VIAS REQUIRE CONDUCTIVE FILL AND PLANARIZE" at 11584.38,1290.84 h60
  text "OUTER XX MIL TRACES REQUIRE 50 OHM SINGLE-ENDED IMPEDANCE" at 11583.39,1127.46 h58
  text "LAYER 2 & 3 (INNER LAYERS) XX MIL WIDE, XX MIL SPACE / TRACES REQUIRE 100 OHM DIFFERENTIAL IMPEDANCE" at 11575.39,891.74 h60
  text ".Layer_Name" at 577,-858.49 h60
M11 Gerber Information:
  lines w10: -292,-930.17 6308,-930.17 ; -292,-726.83 6310,-726.83 ; -292,-523.5 -292,-1133.5 3713,-1133.5 6310,-1133.5 6310,-523.5 -291.5,-523.5 -291.5,-1133.5 1284,-1133.5 ; 2173,-1133.5 2173,-523.5 ; 3440,-726.83 3440,-523.5 ; 4280,-726.83 4280,-523.5 ; 4902,-1140 4902,-937.17
  text "ALL ARTWORK VIEWED FROM TOP SIDE" at -228.5,-655.67 h60
  text "BOARD #:" at 2248,-655.67 h60
  text ".PRJ_Number" at 2793.5,-655.67 h60
  text "REV:" at 3638,-655.67 h60
  text ".PCB_Rev" at 3929.5,-655.67 h60
  text "SVN REV:" at 4476,-655.67 h60
  text ".VersionControl_RevNumber" at 4982,-655.67 h60
  text "LAYER NAME =" at -228.5,-858.49 h60
  text "TID #:" at 2248,-859 h60
  text ".TID" at 2793.5,-859 h60
  text "PLOT NAME =" at -228.5,-1064.34 h60
  text ".plot_File_Name" at 577,-1064.34 h60
  text "GENERATED    :" at 2250,-1064.34 h60
  text ".Print_Date" at 3119.5,-1064.34 h60
  text ".Print_Time" at 3848.5,-1064.34 h60
  text "TEXAS INSTRUMENTS" at 5113,-1064.34 h60
M12 Stackup:
  drawing of 269 lines, arcs and shapes, not listed
  text "Layer" at 1906.14,975.12 h60
  text "Name" at 2316.06,975.12 h60
  text "Material" at 3175.82,975.12 h60
  text "Thickness" at 4035.59,975.12 h60
  text "Constant" at 4685.43,975.12 h60
  text "Board Layer Stack" at 5255.29,975.12 h60
  text "Top Overlay" at 2316.06,855.12 h60
  text "Top Solder" at 2316.06,735.12 h60
  text "Solder Resist" at 3175.82,735.12 h60
  text "0.40mil" at 4035.59,735.12 h60
  text "3.5" at 4685.43,735.12 h60
  text "1" at 1906.14,615.12 h60
  text "Top Layer" at 2316.06,615.12 h60
  text "2.80mil" at 4035.59,615.12 h60
  text "Dielectric 1" at 2316.06,495.12 h60
  text "FR-4 High Tg" at 3175.82,495.12 h60
  text "6.00mil" at 4035.59,495.12 h60
  text "4.8" at 4685.43,495.12 h60
  text "2" at 1906.14,375.12 h60
  text "GND 01" at 2316.06,375.12 h60
  text "1.40mil" at 4035.59,375.12 h60
  text "Dielectric 2" at 2316.06,255.12 h60
  text "FR-4 High Tg" at 3175.82,255.12 h60
  text "40.00mil" at 4035.59,255.12 h60
  text "4.8" at 4685.43,255.12 h60
  text "3" at 1906.14,135.12 h60
  text "GND 02" at 2316.06,135.12 h60
  text "1.40mil" at 4035.59,135.12 h60
  text "Dielectric 3" at 2316.06,15.12 h60
  text "FR-4 High Tg" at 3175.82,15.12 h60
  text "6.00mil" at 4035.59,15.12 h60
  text "4.2" at 4685.43,15.12 h60
  text "4" at 1906.14,-104.88 h60
  text "Bottom Layer" at 2316.06,-104.88 h60
  text "2.80mil" at 4035.59,-104.88 h60
  text "Bottom Solder" at 2316.06,-224.88 h60
  text "Solder Resist" at 3175.82,-224.88 h60
  text "0.40mil" at 4035.59,-224.88 h60
  text "3.5" at 4685.43,-224.88 h60
  text ".Layer_Name" at 577,-858.49 h60
M13 Component Bodies Top:
  text ".Layer_Name" at 577,-858.49 h60
M14 Component Bodies Bottom:
  text ".Layer_Name" at 577,-858.49 h60
M15 Courtyards Top:
  text ".Layer_Name" at 577,-858.49 h60
M16 Courtyards Bottom:
  text ".Layer_Name" at 577,-858.49 h60
Drill Drawing:
  lines w10: 1963.88,1616.8 2019.13,1616.8 2019.13,1672.06 1963.88,1672.06 1963.88,1616.8 ; 1963.88,1754.94 1977.69,1754.94 1991.51,1741.12 2005.32,1754.94 2019.13,1754.94 2005.32,1768.75 2019.13,1782.56 2005.32,1782.56 1991.51,1796.38 1977.69,1782.56 1963.88,1782.56 1977.69,1768.75 1963.88,1754.94 ; 1963.88,1865.44 1991.51,1879.26 2019.13,1865.44 2005.32,1893.07 2019.13,1920.7 1991.51,1906.88 1963.88,1920.7 1977.69,1893.07 1963.88,1865.44 ; 1963.88,2045.02 2019.13,2045.02 1991.51,1989.76 1963.88,2045.02 ; 1963.88,2127.9 1977.69,2127.9 1977.69,2114.08 2005.32,2114.08 2005.32,2127.9 2019.13,2127.9 2019.13,2155.52 2005.32,2155.52 2005.32,2169.34 1977.69,2169.34 1977.69,2155.52 1963.88,2155.52 1963.88,2127.9
  lines w12: 1913.79,1579.51 5145.28,1579.51 ; 1913.79,2201.11 5145.28,2201.11 ; 2251.65,1455.19 2251.65,2325.43 ; 2583.65,1455.19 2583.65,2325.43 ; 3220.22,1455.19 3220.22,2325.43 ; 3479.36,1455.19 3479.36,2325.43 ; 3854.52,1455.19 3854.52,2325.43 ; 4578.85,1455.19 4578.85,2325.43 ; 1913.79,1455.19 5145.28,1455.19 5145.28,2325.43 1913.79,2325.43 1913.79,1455.19
  text "Symbol" at 1988.38,2238.4 h72
  text "Quantity" at 2288.95,2238.4 h72
  text "Finished Hole Size" at 2620.95,2238.4 h72
  text "Plated" at 3257.51,2238.4 h72
  text "Hole Type" at 3516.65,2238.4 h72
  text "Drill Layer Pair" at 3891.81,2238.4 h72
  text "Hole Tolerance" at 4616.14,2238.4 h72
  text "12" at 2288.95,2114.08 h60
  text "7.87mil (0.200mm)" at 2620.95,2114.08 h60
  text "PTH" at 3257.51,2114.08 h60
  text "Round" at 3516.65,2114.08 h60
  text "Top Layer - Bottom Layer" at 3891.81,2114.08 h60
  text "259" at 2288.95,1989.76 h60
  text "10.00mil (0.254mm)" at 2620.95,1989.76 h60
  text "PTH" at 3257.51,1989.76 h60
  text "Round" at 3516.65,1989.76 h60
  text "Top Layer - Bottom Layer" at 3891.81,1989.76 h60
  text "8" at 2288.95,1865.44 h60
  text "40.00mil (1.016mm)" at 2620.95,1865.44 h60
  text "PTH" at 3257.51,1865.44 h60
  text "Round" at 3516.65,1865.44 h60
  text "Top Layer - Bottom Layer" at 3891.81,1865.44 h60
  text "4" at 2288.95,1741.12 h60
  text "49.21mil (1.250mm)" at 2620.95,1741.12 h60
  text "PTH" at 3257.51,1741.12 h60
  text "Round" at 3516.65,1741.12 h60
  text "Top Layer - Bottom Layer" at 3891.81,1741.12 h60
  text "4" at 2288.95,1616.8 h60
  text "98.43mil (2.500mm)" at 2620.95,1616.8 h60
  text "PTH" at 3257.51,1616.8 h60
  text "Round" at 3516.65,1616.8 h60
  text "Top Layer - Bottom Layer" at 3891.81,1616.8 h60
  text "287 Total" at 2288.95,1492.48 h60
  text ".Layer_Name" at 577,-858.49 h60
M17 Embedded Cavity:
  text ".Layer_Name" at 577,-858.49 h60
M18 Embedded Assembly:
  text ".Layer_Name" at 577,-858.49 h60
M19 Embedded Keepout:
  text ".Layer_Name" at 577,-858.49 h60

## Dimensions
0,-400 to 1000,-400 on M2 Board Dimensions
0,0 to -9.84,1771.65 on M2 Board Dimensions
0,0 to 1624.02,-19.68 on M2 Board Dimensions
